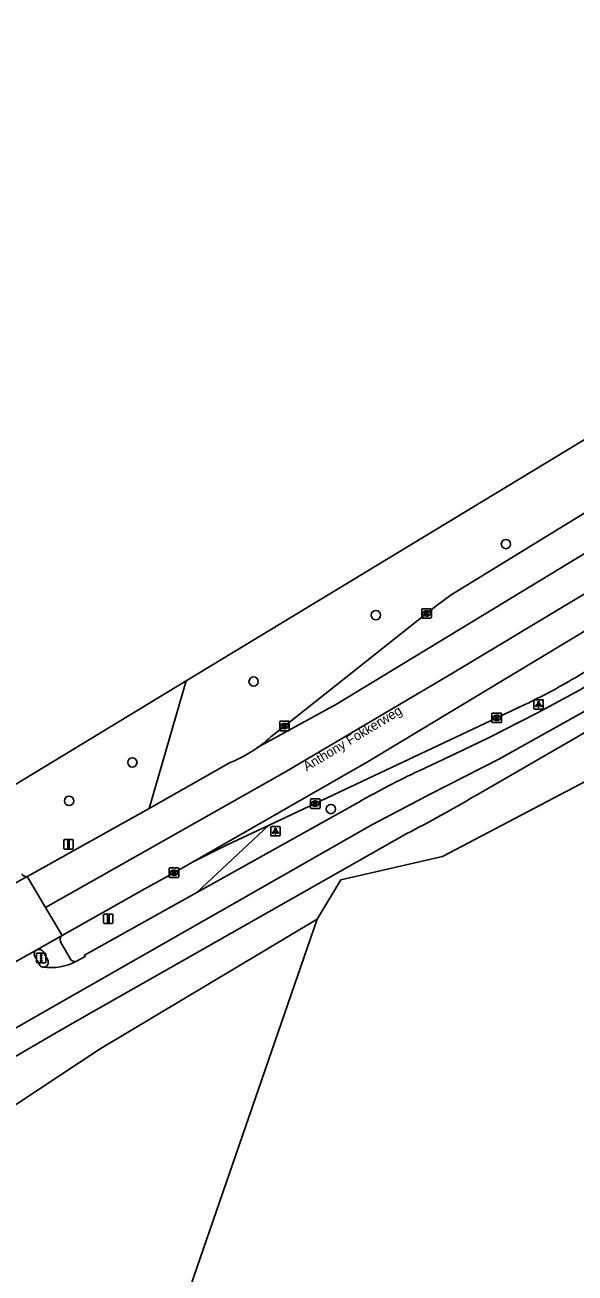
# Model space of a CAD drawing. Extents: x 158132 to 159658, y 385257 to 387209.
# Drawn here: x 158673.1 to 158730.9, y 387064.6 to 387195.6 of the extents above; entities that cross this region are included whole.
import ezdxf

# ---------------------------------------------------------------- set-up
doc = ezdxf.new("R2010")
doc.units = 0
for name, color, linetype in [('IMGEO_Berm_groen', 7, 'Continuous'), ('IMGEO_Boom', 7, 'Continuous'), ('IMGEO_Fietspad_gesloten', 7, 'Continuous'), ('IMGEO_Gemengd_bos', 7, 'Continuous'), ('IMGEO_Kolk', 7, 'Continuous'), ('IMGEO_Lichtpunt', 7, 'Continuous'), ('IMGEO_Openbare_ruimte_label', 7, 'Continuous'), ('IMGEO_Rijbaan_regionaal_gesloten', 7, 'Continuous'), ('IMGEO_Verkeersbordpaal', 7, 'Continuous'), ('IMGEO_Verkeersregelinstallatiepaal', 7, 'Continuous'), ('IMGEO_Voetpad_gesloten', 7, 'Continuous'), ('IMGEO_Voetpad_open', 7, 'Continuous')]:
    doc.layers.add(name, color=color, linetype=linetype)

msp = doc.modelspace()

# ---------------------------------------------------------------- linework, layer by layer
at = {"layer": 'IMGEO_Berm_groen'}
for points in [[(158686.16, 387113.36), (158690.06, 387126.75)], [(158698.7, 387111.56), (158691.19, 387104.54)]]:
    msp.add_lwpolyline(points, dxfattribs=at)
at = {"layer": 'IMGEO_Boom'}
for centre in [(158723.65, 387141.12), (158709.99, 387133.65), (158697.15, 387126.67), (158684.41, 387118.18), (158677.77, 387114.14), (158705.26, 387113.29)]:
    msp.add_circle(centre, 0.489, dxfattribs=at)
at = {"layer": 'IMGEO_Fietspad_gesloten'}
for points in [[(158823.8, 387176.6), (158776.89, 387150.89), (158732.48, 387123.89), (158722.89, 387118.52), (158715.76, 387114.9), (158709.57, 387111.62), (158675.02, 387091.93), (158640.94, 387072.39), (158595.96, 387046.32), (158573.79, 387032.7), (158546.1, 387014.7), (158529.92, 387003.03), (158525.95, 387000), (158514.13, 386990.65), (158513.13, 386989.79), (158506.55, 386984.13), (158500, 386978.13), (158499.21, 386977.39), (158490.61, 386969.27)], [(158809.62, 387171.75), (158780.92, 387155.97), (158775.89, 387153.01), (158772.34, 387150.79), (158731.39, 387125.77), (158726.96, 387123.38), (158721.8, 387120.75), (158718.31, 387119.1), (158714.52, 387117.31)], [(158708.21, 387114.02), (158691.19, 387104.54)], [(158691.19, 387104.54), (158679.38, 387097.95), (158679.47, 387097.81), (158678.54, 387097.3)], [(158674.64, 387096.95), (158674.17, 387097.81)]]:
    msp.add_lwpolyline(points, dxfattribs=at)
for centre, radius, start, end in [((158750.8, 387039.92), 85.47, 115.1204, 119.8902), ((158674.61, 387098.06), 0.503, 119.8027, 209.4603), ((158675.85, 387102.27), 5.64, 261.5723, 298.4604), ((158675.05, 387097.13), 0.447, 204.2706, 265.9912)]:
    msp.add_arc(centre, radius, start, end, dxfattribs=at)
at = {"layer": 'IMGEO_Gemengd_bos'}
for points in [[(158703.82, 387101.71), (158706.29, 387105.85), (158716.99, 387108.3), (158738.31, 387119.52), (158742.44, 387125.91), (158769.67, 387143.32), (158797.02, 387156.73), (158796.65, 387159.48)], [(158703.82, 387101.71), (158681.04, 387088.11), (158663.51, 387076.57), (158660.41, 387074.96), (158660.01, 387075.7), (158644.04, 387067.33), (158614.63, 387050.48), (158601.87, 387043.7)], [(158689.82, 387061.16), (158703.82, 387101.71)]]:
    msp.add_lwpolyline(points, dxfattribs=at)
at = {"layer": 'IMGEO_Kolk'}
for p, q in [((158714.82, 387133.4), (158714.82, 387134.26)), ((158714.89, 387134.33), (158715.74, 387134.33)), ((158715.3, 387134.11), (158715.33, 387134.11)), ((158715.82, 387134.26), (158715.82, 387133.4)), ((158715.74, 387133.33), (158714.89, 387133.33)), ((158715.33, 387133.55), (158715.3, 387133.55)), ((158699.89, 387121.57), (158699.89, 387122.43)), ((158699.96, 387122.5), (158700.82, 387122.5)), ((158700.38, 387122.28), (158700.4, 387122.28)), ((158700.89, 387122.43), (158700.89, 387121.57)), ((158722.18, 387122.44), (158722.18, 387123.29)), ((158722.25, 387123.37), (158723.11, 387123.37)), ((158723.11, 387122.37), (158722.25, 387122.37)), ((158722.67, 387123.15), (158722.69, 387123.15)), ((158722.69, 387122.59), (158722.67, 387122.59)), ((158723.18, 387123.29), (158723.18, 387122.44)), ((158700.82, 387121.5), (158699.96, 387121.5)), ((158700.4, 387121.72), (158700.38, 387121.72)), ((158703.2, 387114.36), (158704.05, 387114.36)), ((158703.12, 387113.43), (158703.12, 387114.28)), ((158704.05, 387113.36), (158703.2, 387113.36)), ((158703.61, 387114.14), (158703.64, 387114.14)), ((158703.63, 387113.58), (158703.61, 387113.58)), ((158704.12, 387114.28), (158704.12, 387113.43)), ((158688.28, 387106.18), (158688.28, 387107.03)), ((158688.35, 387107.1), (158689.2, 387107.1)), ((158688.76, 387106.88), (158688.79, 387106.88)), ((158689.28, 387107.03), (158689.28, 387106.18)), ((158689.2, 387106.1), (158688.35, 387106.1)), ((158688.79, 387106.32), (158688.76, 387106.32))]:
    msp.add_line(p, q, dxfattribs=at)
for points in [[(158714.82, 387133.4), (158714.82, 387134.26)], [(158714.89, 387134.33), (158715.74, 387134.33)], [(158715.14, 387134.03), (158715.26, 387134.03), (158715.26, 387133.88), (158715.39, 387134.03), (158715.55, 387134.03), (158715.41, 387133.88), (158715.56, 387133.63), (158715.41, 387133.63), (158715.32, 387133.79), (158715.26, 387133.73), (158715.26, 387133.63), (158715.14, 387133.63), (158715.14, 387134.03)], [(158715.82, 387134.26), (158715.82, 387133.4)], [(158715.74, 387133.33), (158714.89, 387133.33)], [(158699.89, 387121.57), (158699.89, 387122.43)], [(158699.96, 387122.5), (158700.82, 387122.5)], [(158700.21, 387122.2), (158700.33, 387122.2), (158700.33, 387122.05), (158700.46, 387122.2), (158700.63, 387122.2), (158700.48, 387122.05), (158700.63, 387121.8), (158700.48, 387121.8), (158700.4, 387121.97), (158700.33, 387121.9), (158700.33, 387121.8), (158700.21, 387121.8), (158700.21, 387122.2)], [(158700.89, 387122.43), (158700.89, 387121.57)], [(158722.18, 387122.44), (158722.18, 387123.29)], [(158722.25, 387123.37), (158723.11, 387123.37)], [(158723.11, 387122.37), (158722.25, 387122.37)], [(158722.5, 387123.07), (158722.62, 387123.07), (158722.62, 387122.92), (158722.75, 387123.07), (158722.92, 387123.07), (158722.77, 387122.92), (158722.92, 387122.67), (158722.77, 387122.67), (158722.69, 387122.83), (158722.62, 387122.76), (158722.62, 387122.67), (158722.5, 387122.67), (158722.5, 387123.07)], [(158723.18, 387123.29), (158723.18, 387122.44)], [(158700.82, 387121.5), (158699.96, 387121.5)], [(158703.2, 387114.36), (158704.05, 387114.36)], [(158703.12, 387113.43), (158703.12, 387114.28)], [(158704.05, 387113.36), (158703.2, 387113.36)], [(158703.44, 387114.06), (158703.57, 387114.06), (158703.57, 387113.9), (158703.7, 387114.06), (158703.86, 387114.06), (158703.71, 387113.91), (158703.87, 387113.66), (158703.71, 387113.66), (158703.63, 387113.82), (158703.57, 387113.75), (158703.57, 387113.66), (158703.44, 387113.66), (158703.44, 387114.06)], [(158704.12, 387114.28), (158704.12, 387113.43)], [(158688.28, 387106.18), (158688.28, 387107.03)], [(158688.35, 387107.1), (158689.2, 387107.1)], [(158688.6, 387106.8), (158688.72, 387106.8), (158688.72, 387106.65), (158688.85, 387106.8), (158689.01, 387106.8), (158688.87, 387106.65), (158689.02, 387106.4), (158688.87, 387106.4), (158688.78, 387106.57), (158688.72, 387106.5), (158688.72, 387106.4), (158688.6, 387106.4), (158688.6, 387106.8)], [(158689.28, 387107.03), (158689.28, 387106.18)], [(158689.2, 387106.1), (158688.35, 387106.1)]]:
    msp.add_lwpolyline(points, dxfattribs=at)
for centre, start, end in [((158714.89, 387134.25), 91.552, 178.448), ((158714.89, 387134.25), 91.552, 178.448), ((158715.74, 387134.25), 1.552, 88.448), ((158715.74, 387134.25), 1.552, 88.448), ((158714.89, 387133.41), 181.552, 268.448), ((158714.89, 387133.41), 181.552, 268.448), ((158715.74, 387133.41), 271.552, 358.448), ((158715.74, 387133.41), 271.552, 358.448), ((158699.97, 387122.43), 91.552, 178.448), ((158699.97, 387122.43), 91.552, 178.448), ((158700.81, 387122.43), 1.552, 88.448), ((158700.81, 387122.43), 1.552, 88.448), ((158722.26, 387123.29), 91.552, 178.448), ((158722.26, 387123.29), 91.552, 178.448), ((158722.26, 387122.44), 181.552, 268.448), ((158722.26, 387122.44), 181.552, 268.448), ((158723.1, 387123.29), 1.552, 88.448), ((158723.1, 387123.29), 1.552, 88.448), ((158723.1, 387122.44), 271.552, 358.448), ((158723.1, 387122.44), 271.552, 358.448), ((158699.97, 387121.58), 181.552, 268.448), ((158699.97, 387121.58), 181.552, 268.448), ((158700.81, 387121.58), 271.552, 358.448), ((158700.81, 387121.58), 271.552, 358.448), ((158703.2, 387114.28), 91.552, 178.448), ((158703.2, 387114.28), 91.552, 178.448), ((158704.05, 387114.28), 1.552, 88.448), ((158704.05, 387114.28), 1.552, 88.448), ((158703.2, 387113.43), 181.552, 268.448), ((158703.2, 387113.43), 181.552, 268.448), ((158704.05, 387113.43), 271.552, 358.448), ((158704.05, 387113.43), 271.552, 358.448), ((158688.35, 387107.03), 91.552, 178.448), ((158688.35, 387107.03), 91.552, 178.448), ((158689.2, 387107.03), 1.552, 88.448), ((158689.2, 387107.03), 1.552, 88.448), ((158688.35, 387106.18), 181.552, 268.448), ((158688.35, 387106.18), 181.552, 268.448), ((158689.2, 387106.18), 271.552, 358.448), ((158689.2, 387106.18), 271.552, 358.448)]:
    msp.add_arc(centre, 0.0765, start, end, dxfattribs=at)
for centre, major_axis, ratio, start_param, end_param in [((158715.3, 387133.83), (-0.387, 0.002), 0.722429, 4.712389, 7.853982), ((158715.33, 387133.83), (-0.39, 0.002), 0.717154, 1.570796, 4.712389), ((158700.38, 387122), (-0.387, 0.002), 0.722429, 4.712389, 7.853982), ((158700.4, 387122), (-0.39, 0.002), 0.717154, 1.570796, 4.712389), ((158722.67, 387122.87), (-0.387, 0.002), 0.722429, 4.712389, 7.853982), ((158722.69, 387122.87), (-0.39, 0.002), 0.717154, 1.570796, 4.712389), ((158703.61, 387113.86), (-0.387, 0.002), 0.722429, 4.712389, 7.853982), ((158703.63, 387113.86), (-0.39, 0.002), 0.717154, 1.570796, 4.712389), ((158688.76, 387106.6), (-0.387, 0.002), 0.722429, 4.712389, 7.853982), ((158688.79, 387106.6), (-0.39, 0.002), 0.717154, 1.570796, 4.712389)]:
    msp.add_ellipse(centre, major_axis=major_axis, ratio=ratio, start_param=start_param, end_param=end_param, dxfattribs=at)
at = {"layer": 'IMGEO_Lichtpunt'}
for p, q in [((158726.58, 387124.68), (158726.58, 387123.87)), ((158726.58, 387124.68), (158726.58, 387123.87)), ((158727.48, 387124.77), (158726.67, 387124.77)), ((158727.48, 387124.77), (158726.67, 387124.77)), ((158726.67, 387123.78), (158727.48, 387123.78)), ((158726.67, 387123.78), (158727.48, 387123.78)), ((158727.57, 387123.87), (158727.57, 387124.68)), ((158727.57, 387123.87), (158727.57, 387124.68)), ((158698.95, 387111.36), (158698.95, 387110.55)), ((158698.95, 387111.36), (158698.95, 387110.55)), ((158699.85, 387111.45), (158699.04, 387111.45)), ((158699.85, 387111.45), (158699.04, 387111.45)), ((158699.04, 387110.46), (158699.85, 387110.46)), ((158699.04, 387110.46), (158699.85, 387110.46)), ((158699.95, 387110.55), (158699.95, 387111.36)), ((158699.95, 387110.55), (158699.95, 387111.36))]:
    msp.add_line(p, q, dxfattribs=at)
for points in [[(158726.95, 387124.34), (158726.99, 387124.32), (158726.8, 387124.05), (158726.76, 387124.08), (158726.95, 387124.34)], [(158727.05, 387124.3), (158727.1, 387124.3), (158727.1, 387123.97), (158727.05, 387123.97), (158727.05, 387124.3)], [(158727.16, 387124.32), (158727.2, 387124.34), (158727.39, 387124.08), (158727.35, 387124.05), (158727.16, 387124.32)], [(158699.32, 387111.02), (158699.36, 387110.99), (158699.17, 387110.73), (158699.14, 387110.76), (158699.32, 387111.02)], [(158699.42, 387110.97), (158699.47, 387110.97), (158699.47, 387110.65), (158699.42, 387110.65), (158699.42, 387110.97)], [(158699.53, 387110.99), (158699.57, 387111.02), (158699.76, 387110.76), (158699.72, 387110.73), (158699.53, 387110.99)]]:
    msp.add_lwpolyline(points, dxfattribs=at)
for centre in [(158727.08, 387124.48), (158699.45, 387111.16)]:
    msp.add_circle(centre, 0.0994, dxfattribs=at)
for centre, start, end in [((158726.67, 387124.68), 90, 180), ((158726.67, 387124.68), 90, 180), ((158726.67, 387123.87), 180, 270), ((158726.67, 387123.87), 180, 270), ((158727.48, 387124.68), 0, 90), ((158727.48, 387124.68), 0, 90), ((158727.48, 387123.87), 270, 0), ((158727.48, 387123.87), 270, 360), ((158699.04, 387111.36), 90, 180), ((158699.04, 387111.36), 90, 180), ((158699.04, 387110.55), 180, 270), ((158699.04, 387110.55), 180, 270), ((158699.85, 387111.36), 0, 90), ((158699.85, 387111.36), 0, 90), ((158699.85, 387110.55), 270, 0), ((158699.85, 387110.55), 270, 360)]:
    msp.add_arc(centre, 0.0946, start, end, dxfattribs=at)
at = {"layer": 'IMGEO_Rijbaan_regionaal_gesloten'}
for points in [[(158822.71, 387195.63), (158796, 387179.3), (158734.09, 387141.45), (158705.84, 387124.3), (158697.49, 387119.7)], [(158824.7, 387192.58), (158800.45, 387177.82), (158765.96, 387156.73), (158732.32, 387136.14), (158717.67, 387127.33), (158700.49, 387117.19), (158675.29, 387102.95)], [(158690.06, 387126.75), (158761.35, 387169.93), (158796.99, 387191.8)], [(158826.64, 387189.6), (158788.89, 387166.58), (158750.91, 387143.43), (158709.19, 387118.27), (158690.71, 387107.7)], [(158791.92, 387181.1), (158750.96, 387156.02), (158733.46, 387145.34), (158717.89, 387135.77), (158716.27, 387134.61), (158715.32, 387133.83), (158700.39, 387122), (158698.94, 387120.87)], [(158730.91, 387127.07), (158740.98, 387133.23), (158758.93, 387144.19), (158778.35, 387156.07), (158799.54, 387169.08)], [(158669.08, 387114.04), (158690.06, 387126.75)], [(158698.7, 387111.56), (158703.62, 387113.86), (158722.68, 387122.87), (158725.63, 387124.25)], [(158694.7, 387118.16), (158686.16, 387113.36)], [(158686.16, 387113.36), (158673.51, 387106.27), (158673.36, 387106.21)], [(158690.71, 387107.7), (158694.31, 387109.51), (158698.7, 387111.56)], [(158677.03, 387100.01), (158685.66, 387104.87), (158688.77, 387106.6), (158690.71, 387107.7)], [(158673.36, 387106.21), (158670.77, 387104.76)], [(158673.36, 387106.21), (158675.29, 387102.95)], [(158675.29, 387102.95), (158677.03, 387100.01)], [(158674.36, 387098.5), (158677.03, 387100.01)], [(158671.67, 387096.98), (158672.06, 387097.2), (158674.36, 387098.5)]]:
    msp.add_lwpolyline(points, dxfattribs=at)
for centre, radius, start, end in [((158697.65, 387183.04), 65.1, 295.4546, 300.7185), ((158689.33, 387131.23), 14.14, 305.281, 312.8621), ((158689.33, 387131.21), 14.11, 292.3448, 305.3067)]:
    msp.add_arc(centre, radius, start, end, dxfattribs=at)
at = {"layer": 'IMGEO_Verkeersbordpaal'}
for p, q in [((158677.21, 387109.19), (158677.21, 387109.99)), ((158677.21, 387109.99), (158677.21, 387109.19)), ((158677.31, 387110.09), (158678.1, 387110.09)), ((158678.1, 387110.09), (158677.31, 387110.09)), ((158678.1, 387109.09), (158677.31, 387109.09)), ((158677.31, 387109.09), (158678.1, 387109.09)), ((158678.2, 387109.99), (158678.2, 387109.19)), ((158678.2, 387109.19), (158678.2, 387109.99)), ((158681.39, 387101.36), (158681.39, 387102.16)), ((158681.39, 387102.16), (158681.39, 387101.36)), ((158681.49, 387102.26), (158682.27, 387102.26)), ((158682.27, 387102.26), (158681.49, 387102.26)), ((158682.27, 387101.26), (158681.49, 387101.26)), ((158681.49, 387101.26), (158682.27, 387101.26)), ((158682.37, 387102.16), (158682.37, 387101.36)), ((158682.37, 387101.36), (158682.37, 387102.16))]:
    msp.add_line(p, q, dxfattribs=at)
for points in [[(158677.63, 387109.96), (158677.78, 387109.96), (158677.78, 387109.21), (158677.63, 387109.21), (158677.63, 387109.96)], [(158681.8, 387102.14), (158681.96, 387102.14), (158681.96, 387101.39), (158681.8, 387101.39), (158681.8, 387102.14)]]:
    msp.add_lwpolyline(points, dxfattribs=at)
for centre, start, end in [((158677.31, 387109.99), 90, 180), ((158677.31, 387109.99), 90, 180), ((158677.31, 387109.19), 180, 270), ((158677.31, 387109.19), 180, 270), ((158678.1, 387109.99), 0, 90), ((158678.1, 387109.99), 360, 90), ((158678.1, 387109.19), 270, 0), ((158678.1, 387109.19), 270, 0), ((158681.49, 387102.16), 90, 180), ((158681.49, 387102.16), 90, 180), ((158681.49, 387101.36), 180, 270), ((158681.49, 387101.36), 180, 270), ((158682.27, 387102.16), 0, 90), ((158682.27, 387102.16), 360, 90), ((158682.27, 387101.36), 270, 0), ((158682.27, 387101.36), 270, 0)]:
    msp.add_arc(centre, 0.1, start, end, dxfattribs=at)
at = {"layer": 'IMGEO_Verkeersregelinstallatiepaal'}
for p, q in [((158674.34, 387097.24), (158674.34, 387098.04)), ((158674.34, 387098.04), (158674.34, 387097.24)), ((158674.44, 387098.14), (158675.22, 387098.14)), ((158675.22, 387098.14), (158674.44, 387098.14)), ((158675.32, 387098.04), (158675.32, 387097.24)), ((158675.32, 387097.24), (158675.32, 387098.04)), ((158675.22, 387097.14), (158674.44, 387097.14)), ((158674.44, 387097.14), (158675.22, 387097.14))]:
    msp.add_line(p, q, dxfattribs=at)
for centre in [(158674.83, 387097.93), (158674.83, 387097.64), (158674.83, 387097.35)]:
    msp.add_circle(centre, 0.085, dxfattribs=at)
for centre, start, end in [((158674.44, 387098.04), 90, 180), ((158674.44, 387098.04), 90, 180), ((158675.22, 387098.04), 0, 90), ((158675.22, 387098.04), 360, 90), ((158674.44, 387097.24), 180, 270), ((158674.44, 387097.24), 180, 270), ((158675.22, 387097.24), 270, 0), ((158675.22, 387097.24), 270, 0)]:
    msp.add_arc(centre, 0.1, start, end, dxfattribs=at)
at = {"layer": 'IMGEO_Voetpad_gesloten'}
for points in [[(158720.3, 387114.61), (158731.08, 387120.83), (158733.5, 387122.28), (158774.25, 387147.16), (158777.85, 387149.12), (158796.65, 387159.48)], [(158659.55, 387079.09), (158659.17, 387079.77), (158676.28, 387089.71), (158679.07, 387091.31), (158713.23, 387110.71)]]:
    msp.add_lwpolyline(points, dxfattribs=at)
msp.add_arc((158653.46, 387227.47), 131.17, 297.1084, 300.6309, dxfattribs=at)
at = {"layer": 'IMGEO_Voetpad_open'}
for points in [[(158676.88, 387099.35), (158677.91, 387097.51)], [(158675.52, 387097.41), (158675.04, 387098.33)], [(158675.02, 387096.68), (158675.33, 387096.76)]]:
    msp.add_lwpolyline(points, dxfattribs=at)
for centre, radius, start, end in [((158673.26, 387106.7), 0.501, 204.9814, 281.7237), ((158677.37, 387099.59), 0.541, 128.4825, 206.3868), ((158674.6, 387098.02), 0.532, 35.0069, 116.9604), ((158675.11, 387097.18), 0.472, 298.7718, 29.4312), ((158678.34, 387097.77), 0.5, 210.6116, 292.904)]:
    msp.add_arc(centre, radius, start, end, dxfattribs=at)

# ---------------------------------------------------------------- texts
at = {"layer": 'IMGEO_Openbare_ruimte_label'}
msp.add_text('Anthony Fokkerweg', height=1, rotation=31.2095, dxfattribs=at).set_placement((158702.73, 387117.23))

doc.saveas('drawing.dxf')
